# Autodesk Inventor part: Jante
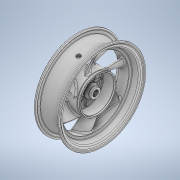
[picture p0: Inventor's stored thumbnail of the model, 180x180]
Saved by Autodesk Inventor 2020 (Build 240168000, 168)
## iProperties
Created: 2003-05
Part Number: Jante
Material: Générique
Document SubType Name: Modeling
Designer: Bruno
Density: 1 g/cm^3
Appearance: Par défaut
Author: Bruno
Sending System: SolidWorks 2011
Last Author: frederic
Last Saved: 2012-02-20
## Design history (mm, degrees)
feature "Congé11"
node "Solide1"
